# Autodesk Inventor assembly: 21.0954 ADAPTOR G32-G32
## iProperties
Created: 2012-10
Part Number: 21.0954 ADAPTOR G32-G32
Document SubType Name: Assembly
Designer: Administrator
Author: Administrator
